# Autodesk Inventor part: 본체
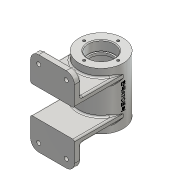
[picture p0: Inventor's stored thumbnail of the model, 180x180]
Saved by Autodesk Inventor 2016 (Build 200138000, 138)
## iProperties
Created: 2017-02
Part Number: 본체
Material: 알루미늄 6061
Document SubType Name: Modeling
Designer: H
Density: 2.7 g/cm^3
Appearance: 알루미늄 - 평지
Mass: 354.768 g
Surface Area: 422.768 cm^2
Volume: 131.396 cm^3
Author: H
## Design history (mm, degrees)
sketch "스케치1"
  geometry: C1 r 27 at (0, 0) reference
  constraints: 1 centre point, 2 other
  dimensions: "d1" = 54 diameter of C1 (derived)
extrude "돌출1" new body sketch "스케치1" stored distance "d2" = 70; taper "d3" = 0 deg
sketch "스케치4"
  geometry: L1 (0, 0)-(-60, 0); L2 (-52, 52)-(-60, 52); L3 (-52, -52)-(-60, -52); L4 (-52, 17)-(-60, 17); L5 (-52, -17)-(-60, -17); L6 (-52, 52)-(-52, 17); L7 (-52, -17)-(-52, -52); L8 (-60, 52)-(-60, 17); L9 (-60, -17)-(-60, -52)
  constraints: 18 end point, 4 parallel, 4 vertical, 1 horizontal
  dimensions: "d8" = 60 distance of L1.start L1.end; "d9" = 52 distance between parallel lines of L1 L2; "d10" = 104 distance between parallel lines of L2 L3; "d15" = 17 distance between parallel lines of L1 L4; "d16" = 17 distance between parallel lines of L1 L5; "d17" = 60 distance from line of L1.start L8; "d18" = 60 distance from line of L1.start L9
extrude "돌출2" join sketch "스케치4" stored distance "d13" = 54; taper "d14" = 0 deg
sketch "스케치5"
  geometry: L1 (-60, 52)-(-52, 52) reference; L2 (-52, 52)-(-52, 17) reference; L3 (-52, 17)-(-60, 17) reference; L4 (-60, 17)-(-60, 52) reference; L5 (-52, -52)-(-60, -52) reference; L6 (-60, -52)-(-60, -17) reference; L7 (-60, -17)-(-52, -17) reference; L8 (-52, -17)-(-52, -52) reference; L9 (-60, 17)-(0, 17); L10 (-60, 25)-(0, 25); L11 (-60, -17)-(0, -17); L12 (-60, -25)-(0, -25); L13 (-60, 25)-(-60, 17); L14 (-60, -17)-(-60, -25); L15 (-27, -35)-(27, -35) reference; L16 (27, 35)-(-27, 35) reference; L17 (0, 25)-(0, 17); L18 (0, -17)-(0, -25); 1 further point
  constraints: 16 end point, 2 collinear, 2 horizontal, 2 parallel
  dimensions: "d19" = 8 distance between parallel lines of L9 L10; "d20" = 8 distance between parallel lines of L11 L12
extrude "돌출3" join sketch "스케치5" stored distance "d21" = 54; taper "d22" = 0 deg
sketch "스케치6"
  geometry: L1 (27, 35)-(-27, 35) reference; L2 (27, -35)-(27, 35) reference; L3 (32, 10)-(-27, 10); L4 (32, 15)-(13.126, 15); L5 (13.126, 15)-(13.126, 10); L6 (-60, 17)-(-60, 52) reference; L7 (32, 15)-(32, 10); L8 (32, 10)-(13.126, 10); 1 further point
  constraints: 10 end point, 2 parallel, 1 collinear, 1 perpendicular, 1 point on line, 1 vertical
  dimensions: "d23" = 25 distance between parallel lines of L1 L3; "d24" = 5 distance between parallel lines of L3 L4; "d26" = 92 distance between parallel lines of L7 L6
revolve "회전1" sketch "스케치6" stored, may be unused: angle "d27" = 90 deg
sketch "스케치8"
  geometry: C1 r 5 at (0, 0) reference; 1 further point
hole "구멍1" sketch "스케치8" at (0, 0) diameter "d38" = 5.188; stored, may be unused: countersink angle "d42" = 90 deg, drill point angle "d44" = 118 deg; dims "d39" = 30, "d40" = 4, "d41" = 2, "d43" = 34
sketch "스케치9"
  geometry: C1 r 27 at (0, 0) reference; A1 r 21 centre (0, 0) between (0, 21) and (21, 0); 2 further points
  constraints: 4 point on circle, 1 centre point, 1 coincident
hole "구멍2" sketch "스케치9" at (0, 21), (21, 0), (0, -21), (-21, 0) diameter "d46" = 3.242; stored, may be unused: countersink angle "d50" = 90 deg, drill point angle "d52" = 118 deg; dims "d47" = 8, "d48" = 4, "d49" = 2, "d51" = 10
node "작업 평면1"
sketch "스케치10"
  geometry: L1 (0, 0)-(0, -40.315); L2 (0, 0)-(-16.339, -25.16); L3 (-11.307, -28.428)-(-1.668, -13.584); L4 (-11.307, -28.428)-(-16.339, -25.16); L5 (-1.668, -13.584)-(-6.7, -10.317); C1 r 27 at (0, 0) reference; 1 further point
  constraints: 10 end point, 1 point on line, 1 vertical
  dimensions: "d59" = 33 deg angle of L2 L1; "d60" = 30 distance of L1.start L2.end; "d62" = 12 diameter of L3 L2
revolve "회전5" stored, may be unused: angle "d63" = 90 deg
sketch "스케치7"
  geometry: L1 (27, 35)-(-27, 35) reference; L2 (-27, -35)-(27, -35) reference; L3 (0, 35)-(0, -35); L4 (0, 35)-(16, 35); L5 (16, 23)-(14, 23); L6 (14, 23)-(14, 20); L7 (16, 35)-(16, 23); L8 (14, 20)-(22, 20); L9 (22, 20)-(22, -20); L10 (22, -20)-(14, -20); L11 (14, -20)-(14, -23); L12 (14, -23)-(16, -23); L13 (16, -23)-(16, -35); L14 (16, -35)-(0, -35); 1 further point
  constraints: 24 end point, 6 perpendicular, 2 horizontal, 2 midpoint, 2 point on line, 1 collinear, 1 vertical
  dimensions: "d28" = 32 diameter of L7 L3; "d29" = 28 diameter of L6 L3; "d30" = 44 diameter of L9 L3; "d31" = 28 diameter of L11 L3; "d32" = 32 diameter of L13 L3; "d33" = 40 distance of L8.end L9.end; "d34" = 12 distance of L4.end L5.start; "d35" = 12 distance of L12.end L13.end; "d36" = 3 distance of L10.end L11.end
revolve "회전4" sketch "스케치7" stored, may be unused: angle "d58" = 90 deg
sketch "스케치11"
  geometry: 1 further point
hole "구멍3" sketch "스케치11" at (0, 0) diameter "d64" = 5.188; stored, may be unused: countersink angle "d68" = 90 deg, drill point angle "d70" = 118 deg; dims "d65" = 20, "d66" = 4, "d67" = 2, "d69" = 24
sketch "스케치12"
  geometry: L1 (0, 0)-(0, -35) reference; L2 (54, 0)-(0, 0) reference; L3 (54, -35)-(54, 0) reference; L4 (54, -35)-(0, -35) reference; L5 (54, -104)-(54, -69) reference; L6 (0, -104)-(54, -104) reference; L7 (0, -69)-(0, -104) reference; L8 (0, -69)-(54, -69) reference; L9 (27, -52)-(27, -126.559); L10 (27, -52)-(68.66, -52); L11 (27, -52)-(-16.754, -52); L12 (27, -52)-(27, 13.79); L13 (68.66, -10)-(27, -10); L14 (27, -10)-(-16.754, -10); L15 (68.66, -94)-(27, -94); L16 (27, -94)-(-16.754, -94); L17 (44, 13.79)-(44, -104); L18 (10, 13.79)-(10, -104); L19 (41.402, -14.5)-(38.804, -10); L20 (38.804, -10)-(41.402, -5.5); L21 (41.402, -5.5)-(46.598, -5.5); L22 (46.598, -5.5)-(49.196, -10); L23 (49.196, -10)-(46.598, -14.5); L24 (46.598, -14.5)-(41.402, -14.5); L25 (41.402, -98.5)-(38.804, -94); L26 (38.804, -94)-(41.402, -89.5); L27 (41.402, -89.5)-(46.598, -89.5); L28 (46.598, -89.5)-(49.196, -94); L29 (49.196, -94)-(46.598, -98.5); L30 (46.598, -98.5)-(41.402, -98.5); L31 (7.402, -98.5)-(4.804, -94); L32 (4.804, -94)-(7.402, -89.5); L33 (7.402, -89.5)-(12.598, -89.5); L34 (12.598, -89.5)-(15.196, -94); L35 (15.196, -94)-(12.598, -98.5); L36 (12.598, -98.5)-(7.402, -98.5); L37 (7.402, -14.5)-(4.804, -10); L38 (4.804, -10)-(7.402, -5.5); L39 (7.402, -5.5)-(12.598, -5.5); L40 (12.598, -5.5)-(15.196, -10); L41 (15.196, -10)-(12.598, -14.5); L42 (12.598, -14.5)-(7.402, -14.5); 9 further points
  constraints: 68 end point, 7 point on line, 4 midpoint, 2 horizontal, 2 vertical, 1 parallel, 54 other
  dimensions: "d71" = 42 distance between parallel lines of L10 L13; "d72" = 42 distance between parallel lines of L10 L15; "d73" = 17 distance between parallel lines of L12 L17; "d74" = 34 distance between parallel lines of L17 L18
extrude "돌출4" cut sketch "스케치12" distance "d79" = 3; taper "d80" = 0 deg
sketch "스케치13"
  geometry: L1 (12.598, -98.5)-(7.402, -98.5) reference; L2 (15.196, -94)-(12.598, -98.5) reference; L3 (12.598, -89.5)-(15.196, -94) reference; L4 (7.402, -89.5)-(12.598, -89.5) reference; L5 (4.804, -94)-(7.402, -89.5) reference; L6 (7.402, -98.5)-(4.804, -94) reference; L7 (46.598, -98.5)-(41.402, -98.5) reference; L8 (49.196, -94)-(46.598, -98.5) reference; L9 (46.598, -89.5)-(49.196, -94) reference; L10 (41.402, -89.5)-(46.598, -89.5) reference; L11 (38.804, -94)-(41.402, -89.5) reference; L12 (41.402, -98.5)-(38.804, -94) reference; L13 (46.598, -14.5)-(41.402, -14.5) reference; L14 (49.196, -10)-(46.598, -14.5) reference; L15 (46.598, -5.5)-(49.196, -10) reference; L16 (41.402, -5.5)-(46.598, -5.5) reference; L17 (38.804, -10)-(41.402, -5.5) reference; L18 (41.402, -14.5)-(38.804, -10) reference; L19 (12.598, -14.5)-(7.402, -14.5) reference; L20 (15.196, -10)-(12.598, -14.5) reference; L21 (12.598, -5.5)-(15.196, -10) reference; L22 (7.402, -5.5)-(12.598, -5.5) reference; L23 (4.804, -10)-(7.402, -5.5) reference; L24 (7.402, -14.5)-(4.804, -10) reference; L25 (10, -98.5)-(10, -5.5); L26 (4.804, -94)-(49.196, -94); L27 (4.804, -10)-(49.196, -10); L28 (44, -98.5)-(44, -5.5); 9 further points
  constraints: 8 end point, 4 coincident, 4 midpoint, 2 perpendicular
hole "구멍4" sketch "스케치13" diameter "d81" = 5; stored, may be unused: countersink angle "d85" = 90 deg, drill point angle "d87" = 118 deg; dims "d82" = 20, "d83" = 4, "d84" = 2, "d86" = 24
chamfer "모따기1" distance "d88" = 1; stored, may be unused: second distance "d89" = 2, angle "d90" = 45 deg
fillet "모깎기1" dims "d91" = 2
fillet "모깎기2" dims "d92" = 2
fillet "모깎기3" dims "d93" = 2
fillet "모깎기4" dims "d100" = 10
fillet "모깎기5" dims "d101" = 2
fillet "모깎기6" dims "d102" = 2
fillet "모깎기7" dims "d103" = 3
fillet "모깎기8" dims "d104" = 0.3
node "작업 평면2"
sketch "스케치14"
  geometry: L1 (27, 35)-(-27, 35) reference; L2 (2.402, 7.767)-(2.402, -7.767); L3 (2.402, -7.767)-(-2.402, -7.767); L4 (-2.402, -7.767)-(-2.402, 7.767); L5 (-2.402, 7.767)-(2.402, 7.767); L6 (0, 35)-(0, -39.597); L7 (0, 0)-(39.539, 0); L8 (27, -35)-(27, 35) reference; L9 (-27, -35)-(-27, 35) reference; 2 further points
  constraints: 4 end point, 3 midpoint, 1 horizontal, 1 horizontal alignment, 1 vertical, 1 vertical alignment, 2 other
feature "엠보싱1" sketch "스케치14" dims "d3" = 0, "d106" = 0.5, "d107" = 0
node "솔리드1"
mirror "대칭1"
node "투영된 루프2"
node "투영된 루프3"
node "투영된 루프4"
node "투영된 루프5"
node "투영된 루프8"
node "투영된 루프9"
node "투영된 루프16"
node "투영된 루프17"
node "투영된 루프18"
node "투영된 루프19"
other parameters: "d11" = 8, "d55" = 6, "d105" = 41
